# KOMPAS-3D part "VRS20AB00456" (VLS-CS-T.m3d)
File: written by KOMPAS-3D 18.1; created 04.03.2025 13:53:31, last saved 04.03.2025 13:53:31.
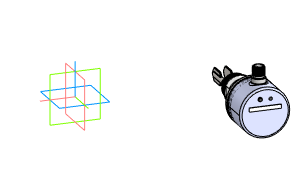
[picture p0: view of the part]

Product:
- Part/product: VRS20AB00456
  - Body: ЛДРѕІеРѕ
  - Body: їЗМе1
  - Body: С№єПЖ¬
  - Body: ПФКѕХЦ
  - Body: ЙПёЗ1
  - Body: №иЅєµжЖ¬
  - Body: ·АЛ®ЅУН·їЗМе
  - Body: PVCГЬ·вµж
  - Body: G34Б¬ЅУМеОАЙъј¶
  - Body: G34ІжМе001

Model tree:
1. Операция без истории:1  (labels: µ№ЅЗ9)
2. Операция без истории:2  (labels: ЗРіэ-РэЧЄ8)
3. Операция без истории:3  (labels: µ№ЅЗ11)
4. Операция без истории:4
5. Операция без истории:5  (labels: µ№ЅЗ7)
6. Операция без истории:6
7. Операция без истории:7
8. Операция без истории:8
9. Операция без истории:9  (labels: µ№ЅЗ3)
10. Операция без истории:10  (labels: РэЧЄ1)
11. Операция без истории:11  (labels: sujiaojian-1-solid1)
12. Операция без истории:12
13. Операция без истории:13
14. Операция без истории:14
15. Операция без истории:15  (labels: µ№ЅЗ9; ЗРіэ-РэЧЄ8; µ№ЅЗ11; µ№ЅЗ7)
